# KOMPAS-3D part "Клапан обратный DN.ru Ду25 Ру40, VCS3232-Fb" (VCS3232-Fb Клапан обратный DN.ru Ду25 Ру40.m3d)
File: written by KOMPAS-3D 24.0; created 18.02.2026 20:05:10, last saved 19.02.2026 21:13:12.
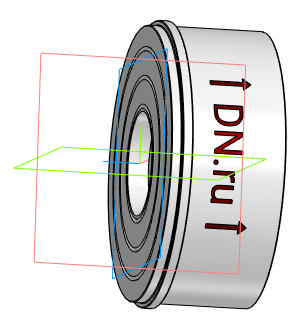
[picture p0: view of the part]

Document properties: Автор: R2D2; Полное имя файла: D:\Работа\Клапаны обратные\VCS3232-Fb Клапан обратный DN.ru Ду15-100\DN25\VCS3232-Fb Клапан обратный DN.ru Ду25 Ру40.m3d

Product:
- Body: Тело 1  | qty 1
    Масса: 0.226516
- Body: Тело 2  | qty 1
    Масса: 0.075056
- Part/product: Клапан обратный DN.ru Ду25 Ру40  | designation VCS3232-Fb
    Масса: 0.37
    Раздел спецификации: Прочие изделия
    Примечание: D100-03707
    additional columns: 1; D100-03707

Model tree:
1. Операция без истории:1
2. Операция без истории:2

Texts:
  Точка начала. Х
  Точка начала. Y
  Точка начала. Z
  VCS3232-Fb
